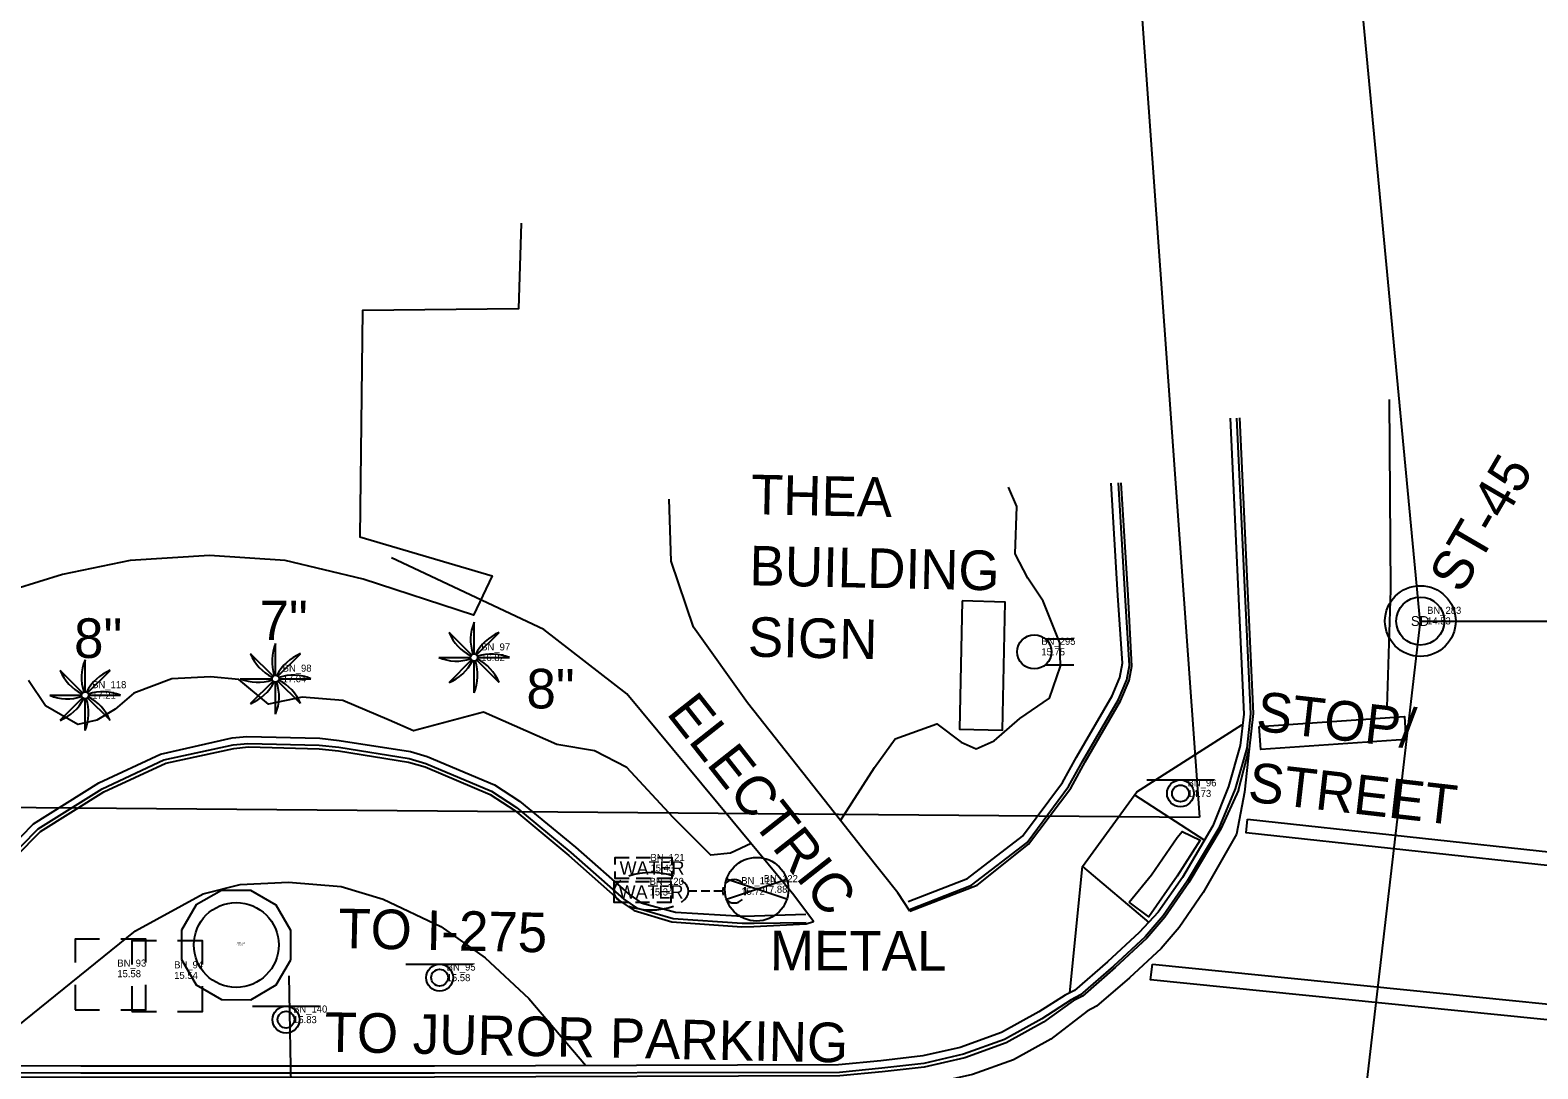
# Model space of a CAD drawing. Extents: x 509744 to 512285, y 1314862 to 1316822.
# Drawn here: x 511322.6 to 511429.2, y 1315641.3 to 1315714.8 of the extents above; entities that cross this region are included whole.
import ezdxf

# ---------------------------------------------------------------- set-up
doc = ezdxf.new("R2010")
doc.units = 0
for name, color, linetype in [('AccessRamp_ep', 7, 'Continuous'), ('Building_ep', 7, 'Continuous'), ('CGBack_ep', 7, 'Continuous'), ('CGep_ep', 7, 'Continuous'), ('CGFace_ep', 7, 'Continuous'), ('CurbRampWarning_ep', 7, 'Continuous'), ('FloodLight_ep', 7, 'Continuous'), ('LandscapeBordr_ep', 7, 'Continuous'), ('Luminaire_ep', 7, 'Continuous'), ('ManholeSW_ep', 7, 'Continuous'), ('MeterWater_ep', 7, 'Continuous'), ('NonPlottingEle_dp', 7, 'Continuous'), ('PavtAsphalt_ep', 7, 'Continuous'), ('PavtAsphaltCrown_ep', 7, 'Continuous'), ('PipeCulvert_ep', 7, 'Continuous'), ('PMRK_ep', 7, 'Continuous'), ('PullBox_ep', 7, 'Continuous'), ('RWLine_ep', 7, 'Continuous'), ('SidewalkBack_ep', 7, 'Continuous'), ('SidewalkFront_ep', 7, 'Continuous'), ('SignColumn_ep', 7, 'Continuous'), ('SignMulti_ep', 7, 'Continuous'), ('SignSingle_ep', 7, 'Continuous'), ('SignTrussOH_ep', 7, 'Continuous'), ('TextElevLabel', 7, 'Continuous'), ('TextPtLabel', 7, 'Continuous'), ('TextTopoLabel_ep', 7, 'Continuous'), ('TextUtilLabel_ep', 7, 'Continuous'), ('TreePalm_ep', 7, 'Continuous'), ('ValveCover_ep', 7, 'Continuous')]:
    doc.layers.add(name, color=color, linetype=linetype)

msp = doc.modelspace()

# ---------------------------------------------------------------- linework, layer by layer
at = {"layer": 'AccessRamp_ep'}
for p, q in [((511400.65, 1315660.66), (511405.6, 1315657.47)), ((511396.96, 1315655.59), (511401.65, 1315651.65))]:
    msp.add_line(p, q, dxfattribs=at)
msp.add_lwpolyline([(511396.08, 1315646.66), (511396.96, 1315655.59), (511400.81, 1315660.89), (511408.24, 1315665.63)], dxfattribs=at)
at = {"layer": 'Building_ep'}
msp.add_lwpolyline([(511357.28, 1315701.09), (511357.09, 1315695.04), (511346.06, 1315694.93), (511345.87, 1315678.92), (511355.23, 1315676.15), (511353.9, 1315673.37), (511346.1, 1315675.92), (511340.59, 1315677.25), (511335.23, 1315677.59), (511329.64, 1315677.25), (511324.85, 1315676.26), (511319.79, 1315674.7)], dxfattribs=at)
at = {"layer": 'CGBack_ep'}
for points in [[(511407.41, 1315687.31), (511408.38, 1315666.38), (511408.11, 1315664.15), (511407.3, 1315661.25), (511406.19, 1315658.47), (511404.04, 1315654.82), (511402.32, 1315652.36), (511400.98, 1315650.94), (511398.74, 1315648.85), (511396.41, 1315646.84), (511395.75, 1315646.49), (511393.88, 1315645.32), (511391.24, 1315643.87), (511388.33, 1315642.81), (511385.68, 1315642.2), (511382.7, 1315641.86), (511379.71, 1315641.58), (511351.15, 1315641.48), (511326.15, 1315641.49), (511301.15, 1315641.52), (511296.97, 1315641.6)], [(511384.65, 1315653.13), (511388.83, 1315654.74), (511392.74, 1315657.74), (511395.56, 1315661.53), (511396.55, 1315663.33), (511399.06, 1315667.66), (511399.62, 1315668.97), (511399.8, 1315669.99), (511399.47, 1315674.76), (511399, 1315682.71)], [(511267.48, 1315652.74), (511270.4, 1315652.79), (511300.39, 1315652.28), (511313.19, 1315652.08), (511317.35, 1315653.44), (511319.27, 1315655.04), (511322.8, 1315658.61), (511327.41, 1315661.51), (511331.78, 1315663.55), (511336.83, 1315664.69), (511337.88, 1315664.8), (511343.03, 1315664.67), (511344.4, 1315664.52), (511349.44, 1315663.73), (511350.62, 1315663.38), (511355.4, 1315661.37), (511357.15, 1315660.23), (511361.12, 1315656.97), (511364.87, 1315653.66), (511365.77, 1315653.04), (511368.2, 1315652.38), (511372.93, 1315652.09), (511373.77, 1315652.1), (511377.41, 1315652.23)]]:
    msp.add_lwpolyline(points, dxfattribs=at)
at = {"layer": 'CGep_ep'}
msp.add_line((511408, 1315661.01), (511408.76, 1315663.92), dxfattribs=at)
msp.add_lwpolyline([(511408, 1315661.01), (511406.76, 1315658.27), (511404.5, 1315654.48), (511402.8, 1315652.01), (511401.53, 1315650.54), (511399.29, 1315648.45), (511396.96, 1315646.44), (511396.3, 1315646.09), (511394.21, 1315644.58), (511391.57, 1315643.12), (511388.66, 1315642.07), (511385.78, 1315641.41), (511382.8, 1315641.07), (511379.81, 1315640.79), (511351.14, 1315640.7), (511326.14, 1315640.67), (511301.14, 1315640.77)], dxfattribs=at)
at = {"layer": 'CGFace_ep'}
for points in [[(511407.86, 1315687.32), (511408.85, 1315666.4), (511408.6, 1315663.98), (511407.76, 1315661.09), (511406.62, 1315658.31), (511404.38, 1315654.57), (511402.67, 1315652.1), (511401.4, 1315650.63), (511399.16, 1315648.55), (511396.83, 1315646.53), (511396.17, 1315646.18), (511394.1, 1315644.82), (511391.46, 1315643.37), (511388.55, 1315642.32), (511385.75, 1315641.67), (511382.77, 1315641.33), (511379.78, 1315641.04), (511351.14, 1315640.99), (511326.14, 1315640.98), (511301.14, 1315641.07), (511296.96, 1315641.13)], [(511384.74, 1315652.56), (511389.12, 1315654.29), (511393.07, 1315657.3), (511395.99, 1315661.25), (511397, 1315663.08), (511399.51, 1315667.41), (511400.11, 1315668.81), (511400.29, 1315669.82), (511399.99, 1315674.78), (511399.52, 1315682.73)], [(511267.51, 1315652.28), (511270.39, 1315652.34), (511300.39, 1315651.82), (511313.18, 1315651.62), (511317.5, 1315653), (511319.6, 1315654.71), (511323.12, 1315658.27), (511327.65, 1315661.1), (511332.01, 1315663.14), (511336.91, 1315664.2), (511337.96, 1315664.31), (511343, 1315664.18), (511344.38, 1315664.03), (511349.35, 1315663.24), (511350.54, 1315662.89), (511355.19, 1315660.92), (511356.94, 1315659.78), (511360.8, 1315656.58), (511364.53, 1315653.29), (511365.43, 1315652.67), (511368.03, 1315651.92), (511372.91, 1315651.6), (511373.75, 1315651.6), (511377.44, 1315651.65)]]:
    msp.add_lwpolyline(points, dxfattribs=at)
at = {"layer": 'CurbRampWarning_ep'}
msp.add_lwpolyline([(511400.26, 1315653.07), (511401.84, 1315655), (511403.66, 1315657.64), (511404.03, 1315658.08), (511405.3, 1315657.46), (511403.67, 1315654.91), (511401.65, 1315652.03)], close=True, dxfattribs=at)
at = {"layer": 'FloodLight_ep'}
for p, q in [((511394.34, 1315671.7), (511396.37, 1315671.7)), ((511394.34, 1315669.86), (511396.37, 1315669.86))]:
    msp.add_line(p, q, dxfattribs=at)
msp.add_circle((511393.56, 1315670.78), 1.21, dxfattribs=at)
at = {"layer": 'LandscapeBordr_ep'}
for points in [[(511379.86, 1315658.85), (511382.27, 1315662.61), (511383.72, 1315664.62), (511386.68, 1315665.69), (511388.4, 1315664.4), (511389.45, 1315663.92), (511390.73, 1315664.49), (511392.54, 1315666.06), (511394.64, 1315667.51), (511395.41, 1315669.78), (511395.38, 1315671.41), (511394.19, 1315674.37), (511393.1, 1315676), (511392.22, 1315677.72), (511392.33, 1315681.07), (511391.73, 1315682.43)], [(511373.54, 1315657.22), (511372.07, 1315656.54), (511370.68, 1315656.4), (511368.03, 1315659.07), (511364.75, 1315662.6), (511362.46, 1315663.78), (511359.79, 1315664.23), (511354.62, 1315666.51), (511349.67, 1315665.2), (511347.95, 1315665.95), (511344.66, 1315667.33), (511341.8, 1315667.58), (511339.4, 1315667.08), (511337.31, 1315668.82), (511335.31, 1315669.01), (511332.57, 1315668.88), (511329.88, 1315667.85), (511328.57, 1315666.72), (511327.27, 1315665.96), (511325.93, 1315665.64), (511323.64, 1315666.96), (511322.43, 1315668.76)]]:
    msp.add_lwpolyline(points, dxfattribs=at)
at = {"layer": 'Luminaire_ep'}
for p, q in [((511369.71, 1315653.85), (511369.11, 1315653.85)), ((511370.61, 1315653.85), (511370.01, 1315653.85)), ((511371.51, 1315653.85), (511370.91, 1315653.85))]:
    msp.add_line(p, q, dxfattribs=at)
for start, end in [(45, 135), (159.9115, 200.0885), (339.9115, 20.0885), (225, 315)]:
    msp.add_arc((511372.34, 1315653.85), 0.825, start, end, dxfattribs=at)
for start_param, end_param in [(5.668326, 6.898045), (4.075781, 5.348997), (2.526733, 3.756452), (0.934187, 2.207405)]:
    msp.add_ellipse((511366.47, 1315653.85), major_axis=(-2.64, 0), ratio=0.5, start_param=start_param, end_param=end_param, dxfattribs=at)
at = {"layer": 'ManholeSW_ep'}
for radius in [2.5, 1.7]:
    msp.add_circle((511420.86, 1315672.96), radius, dxfattribs=at)
at = {"layer": 'MeterWater_ep'}
for points in [[(511363.92, 1315655.74), (511363.92, 1315656.24), (511364.92, 1315656.24)], [(511365.42, 1315656.24), (511366.42, 1315656.24)], [(511366.92, 1315656.24), (511367.92, 1315656.24), (511367.92, 1315655.74)], [(511363.86, 1315654.05), (511363.86, 1315654.55), (511364.86, 1315654.55)], [(511364.92, 1315654.74), (511363.92, 1315654.74), (511363.92, 1315655.24)], [(511365.36, 1315654.55), (511366.36, 1315654.55)], [(511366.42, 1315654.74), (511365.42, 1315654.74)], [(511366.86, 1315654.55), (511367.86, 1315654.55), (511367.86, 1315654.05)], [(511367.92, 1315655.24), (511367.92, 1315654.74), (511366.92, 1315654.74)], [(511364.86, 1315653.05), (511363.86, 1315653.05), (511363.86, 1315653.55)], [(511367.86, 1315653.55), (511367.86, 1315653.05), (511366.86, 1315653.05)], [(511366.36, 1315653.05), (511365.36, 1315653.05)]]:
    msp.add_lwpolyline(points, dxfattribs=at)
at = {"layer": 'PavtAsphalt_ep'}
msp.add_lwpolyline([(511408.07, 1315687.33), (511409.03, 1315666.41), (511408.76, 1315663.92), (511408.43, 1315660.86), (511407.85, 1315657.89), (511405.5, 1315653.76), (511403.8, 1315651.28), (511402.53, 1315649.81), (511400.29, 1315647.73), (511397.96, 1315645.72), (511397.3, 1315645.37), (511394.74, 1315643.38), (511392.1, 1315641.93), (511389.19, 1315640.88), (511385.94, 1315640.16), (511382.96, 1315639.81), (511379.96, 1315639.61), (511351.13, 1315639.43), (511326.13, 1315639.45), (511301.13, 1315639.49)], dxfattribs=at)
at = {"layer": 'PavtAsphaltCrown_ep'}
msp.add_lwpolyline([(511418.65, 1315688.63), (511418.75, 1315675.17), (511418.48, 1315666.87)], dxfattribs=at)
at = {"layer": 'PipeCulvert_ep'}
for q in [(511395.51, 1315941.43), (511414.73, 1315620.3), (511446.26, 1315672.96)]:
    msp.add_line((511420.86, 1315672.96), q, dxfattribs=at)
at = {"layer": 'PMRK_ep'}
for points in [[(511409.46, 1315665.5), (511419.73, 1315666.22), (511419.84, 1315664.59), (511409.58, 1315663.88)], [(511408.65, 1315658.95), (511431.23, 1315656.5), (511431.12, 1315655.53), (511408.55, 1315657.98)], [(511401.91, 1315648.69), (511437.43, 1315645.11), (511437.31, 1315644), (511401.79, 1315647.58)]]:
    msp.add_lwpolyline(points, close=True, dxfattribs=at)
at = {"layer": 'PullBox_ep'}
for points in [[(511327.47, 1315650.47), (511325.73, 1315650.47), (511325.73, 1315648.8)], [(511330.73, 1315648.8), (511330.73, 1315650.47), (511328.97, 1315650.47)], [(511331.48, 1315650.35), (511329.75, 1315650.35), (511329.75, 1315648.68)], [(511334.74, 1315648.68), (511334.74, 1315650.35), (511332.98, 1315650.35)], [(511325.73, 1315647.24), (511325.73, 1315645.47)], [(511328.97, 1315645.47), (511330.73, 1315645.47), (511330.73, 1315647.24)], [(511329.75, 1315647.13), (511329.75, 1315645.35)], [(511332.98, 1315645.35), (511334.74, 1315645.35), (511334.74, 1315647.13)], [(511325.73, 1315645.47), (511327.47, 1315645.47)], [(511329.75, 1315645.35), (511331.48, 1315645.35)]]:
    msp.add_lwpolyline(points, dxfattribs=at)
at = {"layer": 'RWLine_ep'}
for p in [(511390.65, 1315862.25), (511296.13, 1315660.01)]:
    msp.add_line(p, (511405.24, 1315659.09), dxfattribs=at)
at = {"layer": 'SidewalkBack_ep'}
for points in [[(511384.76, 1315652.44), (511389.53, 1315654.29), (511393.16, 1315657.19), (511396.14, 1315661.15), (511397.16, 1315663), (511399.66, 1315667.32), (511400.28, 1315668.75), (511400.46, 1315669.77), (511400.19, 1315674.79), (511399.71, 1315682.74)], [(511384.76, 1315652.44), (511383.91, 1315653.73), (511381.6, 1315656.64), (511379.86, 1315658.85), (511373.28, 1315667.18), (511369.47, 1315672.52), (511367.88, 1315677.19), (511367.75, 1315681.59)], [(511377.44, 1315651.54), (511377.94, 1315651.7), (511376.56, 1315653.58), (511372.24, 1315658.78), (511364.75, 1315667.81), (511358.87, 1315672.37), (511348.11, 1315677.42)], [(511267.52, 1315652.11), (511270.39, 1315652.16), (511300.38, 1315651.57), (511313.18, 1315651.37), (511317.58, 1315652.76), (511319.78, 1315654.53), (511323.29, 1315658.08), (511327.77, 1315660.88), (511332.14, 1315662.92), (511336.95, 1315663.95), (511338, 1315664.06), (511342.99, 1315663.93), (511344.37, 1315663.77), (511349.31, 1315662.99), (511350.49, 1315662.64), (511355.08, 1315660.69), (511356.83, 1315659.55), (511360.64, 1315656.39), (511364.36, 1315653.1), (511365.26, 1315652.48), (511367.94, 1315651.68), (511372.89, 1315651.34), (511373.74, 1315651.35), (511377.44, 1315651.54)]]:
    msp.add_lwpolyline(points, dxfattribs=at)
at = {"layer": 'SidewalkFront_ep'}
msp.add_lwpolyline([(511318.17, 1315641.5), (511330, 1315651.06), (511334.78, 1315653.67), (511337.4, 1315654.32), (511340.82, 1315654.49), (511344.55, 1315654.19), (511347.51, 1315653.3), (511351.59, 1315651.36), (511354.72, 1315649.15), (511357.81, 1315646.26), (511361.85, 1315641.52)], dxfattribs=at)
at = {"layer": 'SignColumn_ep'}
msp.add_line((511337.13, 1315650.05), (511337.13, 1315650.05), dxfattribs=at)
msp.add_lwpolyline([(511340.99, 1315649.01), (511340.99, 1315651.08), (511339.96, 1315652.87), (511338.17, 1315653.91), (511336.09, 1315653.91), (511334.3, 1315652.88), (511333.26, 1315651.09), (511333.26, 1315649.02), (511334.29, 1315647.22), (511336.09, 1315646.19), (511338.16, 1315646.18), (511339.95, 1315647.22)], close=True, dxfattribs=at)
msp.add_circle((511337.13, 1315650.05), 3, dxfattribs=at)
at = {"layer": 'SignMulti_ep'}
msp.add_lwpolyline([(511388.46, 1315674.39), (511388.27, 1315665.32), (511391.31, 1315665.25), (511391.5, 1315674.29)], close=True, dxfattribs=at)
at = {"layer": 'SignSingle_ep'}
for p, q in [((511401.53, 1315661.72), (511406.28, 1315661.72)), ((511349.13, 1315648.69), (511353.88, 1315648.69)), ((511338.27, 1315645.72), (511343.02, 1315645.72))]:
    msp.add_line(p, q, dxfattribs=at)
for centre, radius in [((511403.9, 1315660.77), 0.95), ((511403.9, 1315660.77), 0.594), ((511351.51, 1315647.74), 0.95), ((511351.51, 1315647.74), 0.594), ((511340.65, 1315644.77), 0.95), ((511340.65, 1315644.77), 0.594)]:
    msp.add_circle(centre, radius, dxfattribs=at)
at = {"layer": 'SignTrussOH_ep'}
msp.add_line((511340.85, 1315647.87), (511341.43, 1315613.71), dxfattribs=at)
at = {"layer": 'TreePalm_ep'}
for p, q in [((511353.95, 1315670.63), (511353.95, 1315672.88)), ((511353.77, 1315670.56), (511352.18, 1315672.15)), ((511354.12, 1315670.56), (511355.71, 1315672.15)), ((511339.73, 1315669.06), (511338.14, 1315670.65)), ((511339.91, 1315669.13), (511339.91, 1315671.38)), ((511340.08, 1315669.06), (511341.67, 1315670.65)), ((511326.26, 1315667.88), (511324.67, 1315669.47)), ((511326.44, 1315667.96), (511326.44, 1315670.21)), ((511326.62, 1315667.88), (511328.21, 1315669.47)), ((511351.45, 1315670.38), (511353.7, 1315670.38)), ((511352.18, 1315668.61), (511353.77, 1315670.21)), ((511353.95, 1315667.88), (511353.95, 1315670.13)), ((511355.71, 1315668.61), (511354.12, 1315670.21)), ((511354.2, 1315670.38), (511356.45, 1315670.38)), ((511337.41, 1315668.88), (511339.66, 1315668.88)), ((511338.14, 1315667.12), (511339.73, 1315668.71)), ((511339.91, 1315666.38), (511339.91, 1315668.63)), ((511341.67, 1315667.12), (511340.08, 1315668.71)), ((511340.16, 1315668.88), (511342.41, 1315668.88)), ((511323.94, 1315667.71), (511326.19, 1315667.71)), ((511324.67, 1315665.94), (511326.26, 1315667.53)), ((511326.44, 1315665.21), (511326.44, 1315667.46)), ((511328.21, 1315665.94), (511326.62, 1315667.53)), ((511326.69, 1315667.71), (511328.94, 1315667.71))]:
    msp.add_line(p, q, dxfattribs=at)
for centre in [(511353.95, 1315670.38), (511339.91, 1315668.88), (511326.44, 1315667.71)]:
    msp.add_circle(centre, 0.25, dxfattribs=at)
for centre, start, end in [((511356.95, 1315671.63), 157.3801, 198.2114), ((511355.18, 1315673.39), 202.3801, 243.2114), ((511356.95, 1315669.14), 112.3801, 153.2114), ((511341.14, 1315671.89), 202.3801, 243.2114), ((511342.91, 1315670.13), 157.3801, 198.2114), ((511342.91, 1315667.65), 112.3801, 153.2114), ((511355.2, 1315667.38), 67.3801, 108.2114), ((511327.68, 1315670.71), 202.3801, 243.2114), ((511329.44, 1315668.96), 157.3801, 198.2114), ((511329.45, 1315666.47), 112.3801, 153.2114), ((511352.7, 1315673.38), 247.3801, 288.2114), ((511350.94, 1315671.62), 292.3801, 333.2114), ((511350.95, 1315669.13), 337.3801, 18.2114), ((511352.71, 1315667.38), 22.3801, 63.2114), ((511338.66, 1315671.88), 247.3801, 288.2114), ((511336.9, 1315670.12), 292.3801, 333.2114), ((511336.91, 1315667.63), 337.3801, 18.2114), ((511338.67, 1315665.88), 22.3801, 63.2114), ((511341.16, 1315665.88), 67.3801, 108.2114), ((511325.19, 1315670.71), 247.3801, 288.2114), ((511323.44, 1315668.94), 292.3801, 333.2114), ((511323.44, 1315666.46), 337.3801, 18.2114), ((511325.2, 1315664.7), 22.3801, 63.2114), ((511327.69, 1315664.71), 67.3801, 108.2114)]:
    msp.add_arc(centre, 3.25, start, end, dxfattribs=at)
at = {"layer": 'ValveCover_ep'}
for p, q in [((511371.8, 1315653.28), (511376.07, 1315654.7)), ((511376.07, 1315653.28), (511371.8, 1315654.7))]:
    msp.add_line(p, q, dxfattribs=at)
msp.add_circle((511373.93, 1315653.99), 2.25, dxfattribs=at)

# ---------------------------------------------------------------- texts
at = {"layer": 'ManholeSW_ep'}
msp.add_text('SD', height=0.7, dxfattribs=at).set_placement((511420.19, 1315672.61))
at = {"layer": 'MeterWater_ep'}
for p in [(511364.24, 1315655.02), (511364.17, 1315653.33)]:
    msp.add_text('WATER', height=0.95, dxfattribs=at).set_placement(p)
at = {"layer": 'NonPlottingEle_dp'}
msp.add_text('ST-45', height=2.8, rotation=59.8002, dxfattribs=at).set_placement((511423.78, 1315674.81))
at = {"layer": 'TextElevLabel'}
for s, height, p in [('14.53', 0.5, (511421.34, 1315672.72)), ('16.82', 0.5, (511354.45, 1315670.13)), ('15.75', 0.5, (511394.06, 1315670.53)), ('17.04', 0.5, (511340.41, 1315668.63)), ('17.21', 0.5, (511326.94, 1315667.46)), ('14.73', 0.5, (511404.4, 1315660.52)), ('15.43', 0.5, (511366.42, 1315655.24)), ('15.34', 0.5, (511366.36, 1315653.55)), ('15.72', 0.5, (511372.84, 1315653.6)), ('17.88', 0.5, (511374.43, 1315653.74)), ('15.94', 0.1, (511337.23, 1315650)), ('15.58', 0.5, (511328.72, 1315647.77)), ('15.54', 0.5, (511332.74, 1315647.65)), ('15.58', 0.5, (511352.01, 1315647.49)), ('15.83', 0.5, (511341.15, 1315644.52))]:
    msp.add_text(s, height=height, dxfattribs=at).set_placement(p)
at = {"layer": 'TextPtLabel'}
for s, height, p in [('BN_283', 0.5, (511421.34, 1315673.47)), ('BN_295', 0.5, (511394.06, 1315671.28)), ('BN_97', 0.5, (511354.45, 1315670.88)), ('BN_98', 0.5, (511340.41, 1315669.38)), ('BN_118', 0.5, (511326.94, 1315668.21)), ('BN_96', 0.5, (511404.4, 1315661.27)), ('BN_121', 0.5, (511366.42, 1315655.99)), ('BN_120', 0.5, (511366.36, 1315654.3)), ('BN_119', 0.5, (511372.84, 1315654.35)), ('BN_122', 0.5, (511374.43, 1315654.49)), ('BN_141', 0.1, (511337.23, 1315650.15)), ('BN_93', 0.5, (511328.72, 1315648.52)), ('BN_94', 0.5, (511332.74, 1315648.4)), ('BN_95', 0.5, (511352.01, 1315648.24)), ('BN_140', 0.5, (511341.15, 1315645.27))]:
    msp.add_text(s, height=height, dxfattribs=at).set_placement(p)
at = {"layer": 'TextTopoLabel_ep'}
for s, rotation, p in [('THEA', 358.8088, (511373.5, 1315680.52)), ('BUILDING', 358.8088, (511373.4, 1315675.49)), ('SIGN', 358.8088, (511373.29, 1315670.45)), ('STOP/', 353.462, (511409.18, 1315665.22)), ('STREET', 353.462, (511408.6, 1315660.21)), ('TO I-275', 358.8088, (511344.32, 1315649.83)), ('TO JUROR PARKING', 358.8088, (511343.35, 1315642.5))]:
    msp.add_text(s, height=2.8, rotation=rotation, dxfattribs=at).set_placement(p)
for s, p in [('7"', (511338.78, 1315671.61)), ('8"', (511325.66, 1315670.35)), ('8"', (511357.65, 1315666.78))]:
    msp.add_text(s, height=2.8, dxfattribs=at).set_placement(p)
at = {"layer": 'TextUtilLabel_ep'}
for s, rotation, p in [('ELECTRIC', 308.2352, (511367.49, 1315666.43)), ('METAL', 359.854, (511374.86, 1315648.26))]:
    msp.add_text(s, height=2.8, rotation=rotation, dxfattribs=at).set_placement(p)

doc.saveas('drawing.dxf')
